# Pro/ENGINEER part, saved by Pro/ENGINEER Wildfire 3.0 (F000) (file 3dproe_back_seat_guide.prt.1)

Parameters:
  DESCRIPTION = "COMPRESSION NUT - 10"
  MODELED_BY = "L. CONARD"
  PTC_COMMON_NAME = "COMPRESSION NUT - 10"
